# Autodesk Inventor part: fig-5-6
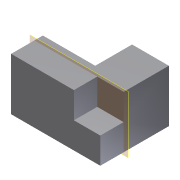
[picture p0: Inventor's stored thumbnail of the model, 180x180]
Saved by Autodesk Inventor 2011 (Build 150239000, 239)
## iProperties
Created: 2010-02
Part Number: fig-5-6
Document SubType Name: Modeling
Designer: CADSoft
Density: 1 g/cm^3
Author: CADSoft
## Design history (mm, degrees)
sketch "Sketch1"
  geometry: L1 (0, 26.227)-(0, 12.145); L2 (0, 12.145)-(-20.026, 12.145); L3 (-20.026, 12.145)-(-20.026, 0); L4 (-20.026, 0)-(14.083, 0); L5 (14.083, 0)-(14.083, 26.227); L6 (14.083, 26.227)-(0, 26.227); 1 further point
  constraints: 12 end point
extrude "Extrusion1" new body sketch "Sketch1" distance "d0" = 20; taper "d1" = 0 deg
sketch "Sketch2"
  geometry: L1 (14.083, 0)-(3.983, 0); L2 (3.983, 0)-(3.983, 8.922); L3 (3.983, 8.922)-(14.083, 8.922); L4 (14.083, 8.922)-(14.083, 0); 1 further point
  constraints: 8 end point
extrude "Extrusion2" cut sketch "Sketch2" distance "d2" = 10; taper "d3" = 0 deg
workplane "Work Plane1"
body "Solid1"
